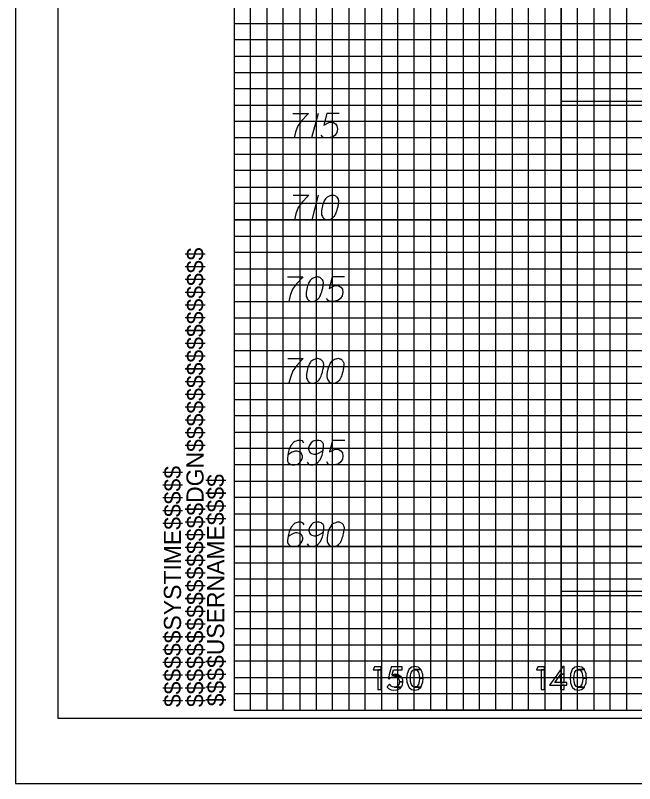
# Model space of a CAD drawing. Extents: x -13 to 323, y -5 to 1431.
# Drawn here: x -13.4 to 24.5, y 435.5 to 482.5 of the extents above; entities that cross this region are included whole.
import ezdxf

# ---------------------------------------------------------------- set-up
doc = ezdxf.new("R2010")
doc.units = 0
for name, color, linetype in [('Prop XS Elevation Labels', 7, 'Continuous'), ('Prop XS Offset Labels', 7, 'Continuous'), ('Scratch_Level_3', 7, 'Continuous'), ('Sheet Cross Section CELL', 7, 'Continuous'), ('Sheet Cross Section Grid Major CELL', 7, 'Continuous'), ('Sheet Cross Section Grid Middle CELL', 7, 'Continuous'), ('Sheet Cross Section Grid Minor 1 CELL', 7, 'Continuous'), ('Sheet Cross Section Grid Minor 2 CELL', 7, 'Continuous'), ('Sheet Cutting Line CELL', 7, 'Continuous'), ('Sheet DOT Grid CELL', 7, 'Continuous'), ('Sheet Plot Border Inside CELL', 7, 'Continuous'), ('Sheet Plot Border Outside CELL', 7, 'Continuous')]:
    doc.layers.add(name, color=color, linetype=linetype)

msp = doc.modelspace()

# ---------------------------------------------------------------- linework, layer by layer
at = {"layer": 'Prop XS Elevation Labels'}
for p, q in [((5.124, 476.5), (4.723, 475)), ((5.142, 471.5), (4.74, 470))]:
    msp.add_line(p, q, dxfattribs=at)
for points in [[(3.589, 476.5), (4.533, 476.5), (4.474, 476.441), (4.132, 476.075), (3.896, 475.744), (3.754, 475.354), (3.659, 475)], [(6.411, 476.5), (5.667, 476.5), (5.478, 475.791), (5.821, 475.969), (6.022, 475.969), (6.187, 475.862), (6.282, 475.744), (6.305, 475.543), (6.27, 475.342), (6.175, 475.177), (6.01, 475.047), (5.726, 475), (5.514, 475), (5.408, 475.047), (5.313, 475.177)], [(3.606, 471.5), (4.551, 471.5), (4.492, 471.441), (4.149, 471.075), (3.913, 470.744), (3.772, 470.354), (3.677, 470)], [(6.039, 471.5), (6.016, 471.5), (5.945, 471.488), (5.898, 471.476), (5.862, 471.465), (5.803, 471.441), (5.732, 471.406), (5.673, 471.37), (5.614, 471.323), (5.579, 471.276), (5.543, 471.217), (5.508, 471.158), (5.472, 471.087), (5.449, 471.039), (5.425, 470.969), (5.39, 470.85), (5.354, 470.673), (5.331, 470.531), (5.331, 470.402), (5.343, 470.307), (5.39, 470.201), (5.425, 470.142), (5.484, 470.071), (5.555, 470.024), (5.591, 470.012), (5.661, 470), (5.72, 470), (5.815, 470.012), (5.898, 470.035), (5.957, 470.071), (6.039, 470.13), (6.075, 470.165), (6.122, 470.213), (6.157, 470.26), (6.181, 470.295), (6.205, 470.354), (6.217, 470.378), (6.24, 470.437), (6.264, 470.508), (6.287, 470.579), (6.299, 470.626), (6.311, 470.661), (6.323, 470.709), (6.347, 470.815), (6.358, 470.874), (6.37, 470.933), (6.382, 471.016), (6.394, 471.122), (6.394, 471.158), (6.382, 471.205), (6.37, 471.252), (6.335, 471.323), (6.299, 471.37), (6.264, 471.406), (6.217, 471.441), (6.169, 471.465), (6.134, 471.476), (6.098, 471.488), (6.039, 471.5)], [(3.258, 466.5), (4.203, 466.5), (4.144, 466.441), (3.801, 466.075), (3.565, 465.744), (3.423, 465.354), (3.329, 465)], [(5.1, 466.5), (5.077, 466.5), (5.006, 466.488), (4.959, 466.476), (4.923, 466.465), (4.864, 466.441), (4.793, 466.406), (4.734, 466.37), (4.675, 466.323), (4.64, 466.276), (4.604, 466.217), (4.569, 466.158), (4.534, 466.087), (4.51, 466.039), (4.486, 465.969), (4.451, 465.85), (4.415, 465.673), (4.392, 465.531), (4.392, 465.402), (4.404, 465.307), (4.451, 465.201), (4.486, 465.142), (4.545, 465.071), (4.616, 465.024), (4.652, 465.012), (4.723, 465), (4.781, 465), (4.876, 465.012), (4.959, 465.035), (5.018, 465.071), (5.1, 465.13), (5.136, 465.165), (5.183, 465.213), (5.219, 465.26), (5.242, 465.295), (5.266, 465.354), (5.278, 465.378), (5.301, 465.437), (5.325, 465.508), (5.349, 465.579), (5.36, 465.626), (5.372, 465.661), (5.384, 465.709), (5.408, 465.815), (5.419, 465.874), (5.431, 465.933), (5.443, 466.016), (5.455, 466.122), (5.455, 466.158), (5.443, 466.205), (5.431, 466.252), (5.396, 466.323), (5.36, 466.37), (5.325, 466.406), (5.278, 466.441), (5.23, 466.465), (5.195, 466.476), (5.16, 466.488), (5.1, 466.5)], [(6.742, 466.5), (5.998, 466.5), (5.809, 465.791), (6.152, 465.969), (6.352, 465.969), (6.518, 465.862), (6.612, 465.744), (6.636, 465.543), (6.6, 465.342), (6.506, 465.177), (6.341, 465.047), (6.057, 465), (5.845, 465), (5.738, 465.047), (5.644, 465.177)], [(3.276, 461.5), (4.22, 461.5), (4.161, 461.441), (3.819, 461.075), (3.583, 460.744), (3.441, 460.354), (3.346, 460)], [(5.118, 461.5), (5.094, 461.5), (5.024, 461.488), (4.977, 461.476), (4.941, 461.465), (4.882, 461.441), (4.811, 461.406), (4.752, 461.37), (4.693, 461.323), (4.658, 461.276), (4.622, 461.217), (4.587, 461.158), (4.551, 461.087), (4.528, 461.039), (4.504, 460.969), (4.469, 460.85), (4.433, 460.673), (4.409, 460.531), (4.409, 460.402), (4.421, 460.307), (4.469, 460.201), (4.504, 460.142), (4.563, 460.071), (4.634, 460.024), (4.669, 460.012), (4.74, 460), (4.799, 460), (4.894, 460.012), (4.977, 460.035), (5.036, 460.071), (5.118, 460.13), (5.154, 460.165), (5.201, 460.213), (5.236, 460.26), (5.26, 460.295), (5.283, 460.354), (5.295, 460.378), (5.319, 460.437), (5.342, 460.508), (5.366, 460.579), (5.378, 460.626), (5.39, 460.661), (5.402, 460.709), (5.425, 460.815), (5.437, 460.874), (5.449, 460.933), (5.461, 461.016), (5.473, 461.122), (5.473, 461.158), (5.461, 461.205), (5.449, 461.252), (5.413, 461.323), (5.378, 461.37), (5.342, 461.406), (5.295, 461.441), (5.248, 461.465), (5.213, 461.476), (5.177, 461.488), (5.118, 461.5)], [(6.37, 461.5), (6.346, 461.5), (6.276, 461.488), (6.228, 461.476), (6.193, 461.465), (6.134, 461.441), (6.063, 461.406), (6.004, 461.37), (5.945, 461.323), (5.909, 461.276), (5.874, 461.217), (5.838, 461.158), (5.803, 461.087), (5.779, 461.039), (5.756, 460.969), (5.721, 460.85), (5.685, 460.673), (5.661, 460.531), (5.661, 460.402), (5.673, 460.307), (5.721, 460.201), (5.756, 460.142), (5.815, 460.071), (5.886, 460.024), (5.921, 460.012), (5.992, 460), (6.051, 460), (6.146, 460.012), (6.228, 460.035), (6.287, 460.071), (6.37, 460.13), (6.406, 460.165), (6.453, 460.213), (6.488, 460.26), (6.512, 460.295), (6.535, 460.354), (6.547, 460.378), (6.571, 460.437), (6.594, 460.508), (6.618, 460.579), (6.63, 460.626), (6.642, 460.661), (6.653, 460.709), (6.677, 460.815), (6.689, 460.874), (6.701, 460.933), (6.713, 461.016), (6.724, 461.122), (6.724, 461.158), (6.713, 461.205), (6.701, 461.252), (6.665, 461.323), (6.63, 461.37), (6.594, 461.406), (6.547, 461.441), (6.5, 461.465), (6.464, 461.476), (6.429, 461.488), (6.37, 461.5)], [(4.262, 456.335), (4.168, 456.465), (4.061, 456.5), (3.896, 456.5), (3.778, 456.453), (3.707, 456.429), (3.648, 456.394), (3.459, 456.181), (3.329, 455.898), (3.294, 455.744), (3.246, 455.402), (3.246, 455.224), (3.294, 455.154), (3.388, 455.059), (3.423, 455.035), (3.542, 455), (3.695, 455), (3.813, 455.024), (3.896, 455.047), (4.014, 455.142), (4.132, 455.331), (4.168, 455.449), (4.168, 455.543), (4.109, 455.697), (4.061, 455.756), (3.979, 455.803), (3.837, 455.839), (3.73, 455.839), (3.601, 455.803), (3.518, 455.768), (3.376, 455.673), (3.305, 455.614), (3.27, 455.579)], [(4.451, 455.165), (4.545, 455.035), (4.652, 455), (4.817, 455), (4.935, 455.047), (5.006, 455.071), (5.065, 455.106), (5.254, 455.319), (5.384, 455.602), (5.419, 455.756), (5.467, 456.098), (5.467, 456.276), (5.419, 456.346), (5.325, 456.441), (5.289, 456.465), (5.171, 456.5), (5.018, 456.5), (4.9, 456.476), (4.817, 456.453), (4.699, 456.358), (4.581, 456.169), (4.545, 456.051), (4.545, 455.957), (4.604, 455.803), (4.652, 455.744), (4.734, 455.697), (4.876, 455.661), (4.982, 455.661), (5.112, 455.697), (5.195, 455.732), (5.337, 455.827), (5.408, 455.886), (5.443, 455.921)], [(6.754, 456.5), (6.01, 456.5), (5.821, 455.791), (6.163, 455.969), (6.364, 455.969), (6.529, 455.862), (6.624, 455.744), (6.647, 455.543), (6.612, 455.342), (6.517, 455.177), (6.352, 455.047), (6.069, 455), (5.856, 455), (5.75, 455.047), (5.655, 455.177)], [(4.28, 451.335), (4.185, 451.465), (4.079, 451.5), (3.914, 451.5), (3.795, 451.453), (3.725, 451.429), (3.666, 451.394), (3.477, 451.181), (3.347, 450.898), (3.311, 450.744), (3.264, 450.402), (3.264, 450.224), (3.311, 450.154), (3.406, 450.059), (3.441, 450.035), (3.559, 450), (3.713, 450), (3.831, 450.024), (3.914, 450.047), (4.032, 450.142), (4.15, 450.331), (4.185, 450.449), (4.185, 450.543), (4.126, 450.697), (4.079, 450.756), (3.996, 450.803), (3.854, 450.839), (3.748, 450.839), (3.618, 450.803), (3.536, 450.768), (3.394, 450.673), (3.323, 450.614), (3.288, 450.579)], [(4.468, 450.165), (4.563, 450.035), (4.669, 450), (4.835, 450), (4.953, 450.047), (5.024, 450.071), (5.083, 450.106), (5.272, 450.319), (5.401, 450.602), (5.437, 450.756), (5.484, 451.098), (5.484, 451.276), (5.437, 451.346), (5.342, 451.441), (5.307, 451.465), (5.189, 451.5), (5.036, 451.5), (4.917, 451.476), (4.835, 451.453), (4.717, 451.358), (4.598, 451.169), (4.563, 451.051), (4.563, 450.957), (4.622, 450.803), (4.669, 450.744), (4.752, 450.697), (4.894, 450.661), (5, 450.661), (5.13, 450.697), (5.213, 450.732), (5.354, 450.827), (5.425, 450.886), (5.461, 450.921)], [(6.382, 451.5), (6.358, 451.5), (6.287, 451.488), (6.24, 451.476), (6.204, 451.465), (6.145, 451.441), (6.074, 451.406), (6.015, 451.37), (5.956, 451.323), (5.921, 451.276), (5.885, 451.217), (5.85, 451.158), (5.815, 451.087), (5.791, 451.039), (5.767, 450.969), (5.732, 450.85), (5.697, 450.673), (5.673, 450.531), (5.673, 450.402), (5.685, 450.307), (5.732, 450.201), (5.767, 450.142), (5.827, 450.071), (5.897, 450.024), (5.933, 450.012), (6.004, 450), (6.063, 450), (6.157, 450.012), (6.24, 450.035), (6.299, 450.071), (6.382, 450.13), (6.417, 450.165), (6.464, 450.213), (6.5, 450.26), (6.523, 450.295), (6.547, 450.354), (6.559, 450.378), (6.582, 450.437), (6.606, 450.508), (6.63, 450.579), (6.642, 450.626), (6.653, 450.661), (6.665, 450.709), (6.689, 450.815), (6.701, 450.874), (6.712, 450.933), (6.724, 451.016), (6.736, 451.122), (6.736, 451.158), (6.724, 451.205), (6.712, 451.252), (6.677, 451.323), (6.642, 451.37), (6.606, 451.406), (6.559, 451.441), (6.512, 451.465), (6.476, 451.476), (6.441, 451.488), (6.382, 451.5)]]:
    msp.add_lwpolyline(points, dxfattribs=at)
at = {"layer": 'Prop XS Offset Labels'}
for points in [[(8.581, 442.641), (8.492, 442.459), (8.99, 442.459), (8.99, 442.641)], [(8.781, 442.459), (8.781, 441.25), (8.99, 441.25), (8.99, 442.459)], [(9.427, 441.94), (9.424, 441.928), (9.495, 441.928), (9.508, 441.94), (9.524, 441.954), (9.595, 441.997), (9.627, 442.007), (9.697, 442.029), (9.811, 442.035), (10.219, 442.035), (10.211, 442.05), (10.076, 442.145), (9.655, 442.145), (9.658, 442.158), (9.658, 442.158), (9.663, 442.178), (9.738, 442.456), (10.263, 442.456), (10.263, 442.641), (9.6, 442.641), (9.554, 442.456), (9.486, 442.178), (9.481, 442.158), (9.478, 442.145), (9.454, 442.05), (9.451, 442.035), (9.449, 442.029), (9.444, 442.007), (9.441, 441.997), (9.431, 441.954)], [(10.851, 441.255), (11.051, 441.214), (11.245, 441.255), (11.256, 441.257), (11.422, 441.409), (11.047, 441.409), (11.038, 441.411), (11.033, 441.413), (10.928, 441.442), (10.841, 441.555), (10.841, 441.556), (10.841, 441.556), (10.813, 441.657), (10.813, 441.659), (10.793, 441.732), (10.792, 441.736), (10.774, 441.939), (10.774, 441.941), (10.774, 441.943), (10.792, 442.145), (10.812, 442.222), (10.813, 442.224), (10.839, 442.322), (10.84, 442.325), (10.928, 442.44), (11.041, 442.469), (11.045, 442.47), (11.055, 442.473), (11.425, 442.473), (11.262, 442.622), (11.254, 442.624), (11.053, 442.668), (11.053, 442.668), (10.845, 442.624), (10.843, 442.622), (10.681, 442.473), (10.678, 442.47), (10.678, 442.469), (10.665, 442.44), (10.618, 442.325), (10.617, 442.322), (10.577, 442.224), (10.576, 442.222), (10.568, 442.145), (10.547, 441.943), (10.547, 441.941), (10.547, 441.939), (10.567, 441.736), (10.568, 441.732), (10.575, 441.659), (10.575, 441.657), (10.616, 441.556), (10.617, 441.555), (10.663, 441.442), (10.675, 441.413), (10.676, 441.411), (10.679, 441.409), (10.848, 441.257)], [(11.312, 442.145), (11.328, 441.943), (11.555, 441.943), (11.536, 442.145), (11.528, 442.222), (11.527, 442.224), (11.527, 442.224), (11.488, 442.322), (11.488, 442.322), (11.487, 442.325), (11.441, 442.44), (11.44, 442.44), (11.429, 442.469), (11.428, 442.47), (11.425, 442.473), (11.055, 442.473), (11.065, 442.47), (11.068, 442.469), (11.175, 442.44), (11.262, 442.325), (11.265, 442.322), (11.291, 442.224), (11.291, 442.222)], [(18.581, 442.641), (18.492, 442.459), (18.99, 442.459), (18.99, 442.641)], [(18.781, 442.459), (18.781, 441.25), (18.99, 441.25), (18.99, 442.459)], [(19.411, 441.693), (19.297, 441.534), (20.35, 441.534), (20.35, 441.693), (19.618, 441.693), (19.878, 442.059), (19.935, 442.139), (19.977, 442.199), (20.179, 442.199), (20.179, 442.668), (20.114, 442.668), (19.775, 442.199), (19.733, 442.139), (19.675, 442.059)], [(20.851, 441.255), (21.051, 441.214), (21.245, 441.255), (21.256, 441.257), (21.422, 441.409), (21.047, 441.409), (21.038, 441.411), (21.033, 441.413), (20.928, 441.442), (20.841, 441.555), (20.841, 441.556), (20.841, 441.556), (20.813, 441.657), (20.813, 441.659), (20.793, 441.732), (20.792, 441.736), (20.774, 441.939), (20.774, 441.941), (20.774, 441.943), (20.792, 442.145), (20.812, 442.222), (20.813, 442.224), (20.839, 442.322), (20.84, 442.325), (20.928, 442.44), (21.041, 442.469), (21.045, 442.47), (21.055, 442.473), (21.425, 442.473), (21.262, 442.622), (21.254, 442.624), (21.053, 442.668), (21.053, 442.668), (20.845, 442.624), (20.843, 442.622), (20.681, 442.473), (20.678, 442.47), (20.678, 442.469), (20.665, 442.44), (20.618, 442.325), (20.617, 442.322), (20.577, 442.224), (20.576, 442.222), (20.568, 442.145), (20.547, 441.943), (20.547, 441.941), (20.547, 441.939), (20.567, 441.736), (20.567, 441.732), (20.575, 441.659), (20.575, 441.657), (20.616, 441.556), (20.617, 441.555), (20.663, 441.442), (20.675, 441.413), (20.676, 441.411), (20.679, 441.409), (20.848, 441.257)], [(21.312, 442.145), (21.328, 441.943), (21.555, 441.943), (21.536, 442.145), (21.528, 442.222), (21.527, 442.224), (21.527, 442.224), (21.488, 442.322), (21.488, 442.322), (21.487, 442.325), (21.441, 442.44), (21.44, 442.44), (21.429, 442.469), (21.428, 442.47), (21.425, 442.473), (21.055, 442.473), (21.065, 442.47), (21.068, 442.469), (21.175, 442.44), (21.262, 442.325), (21.265, 442.322), (21.291, 442.224), (21.291, 442.222)], [(9.424, 441.928), (9.482, 441.916), (9.495, 441.928)], [(9.692, 442.158), (9.655, 442.145), (10.076, 442.145), (10.058, 442.158), (9.961, 442.178), (9.75, 442.178)], [(9.888, 442.192), (9.75, 442.178), (9.96, 442.178), (9.888, 442.192)], [(10.083, 441.841), (10.105, 441.721), (10.318, 441.721), (10.307, 441.841), (10.307, 441.841), (10.303, 441.881), (10.284, 441.916), (10.278, 441.928), (10.271, 441.94), (10.263, 441.954), (10.24, 441.997), (10.235, 442.007), (10.223, 442.029), (10.219, 442.035), (9.811, 442.035), (9.838, 442.029), (9.928, 442.007), (9.943, 441.997), (10.003, 441.954), (10.024, 441.94), (10.031, 441.928), (10.038, 441.916), (10.059, 441.881)], [(11.058, 441.411), (11.047, 441.409), (11.422, 441.409), (11.425, 441.411), (11.426, 441.413), (11.438, 441.442), (11.485, 441.555), (11.485, 441.556), (11.527, 441.657), (11.528, 441.659), (11.535, 441.732), (11.535, 441.736), (11.555, 441.939), (11.556, 441.941), (11.555, 441.943), (11.328, 441.943), (11.328, 441.941), (11.328, 441.939), (11.312, 441.736), (11.312, 441.732), (11.292, 441.659), (11.291, 441.657), (11.264, 441.556), (11.263, 441.555), (11.175, 441.442), (11.063, 441.413)], [(19.97, 442.059), (19.97, 441.693), (20.179, 441.693), (20.179, 442.059), (20.179, 442.139), (20.179, 442.199), (19.977, 442.199), (19.973, 442.139)], [(21.058, 441.411), (21.047, 441.409), (21.422, 441.409), (21.425, 441.411), (21.426, 441.413), (21.438, 441.442), (21.485, 441.555), (21.485, 441.556), (21.527, 441.657), (21.528, 441.659), (21.535, 441.732), (21.535, 441.736), (21.555, 441.939), (21.556, 441.941), (21.555, 441.943), (21.328, 441.943), (21.328, 441.941), (21.328, 441.939), (21.312, 441.736), (21.312, 441.732), (21.292, 441.659), (21.291, 441.657), (21.264, 441.556), (21.263, 441.555), (21.175, 441.442), (21.063, 441.413)], [(9.626, 441.233), (9.762, 441.214), (9.959, 441.233), (9.968, 441.237), (10.091, 441.297), (10.091, 441.297), (10.141, 441.321), (10.185, 441.375), (10.204, 441.399), (9.793, 441.399), (9.683, 441.418), (9.682, 441.419), (9.679, 441.42), (9.596, 441.466), (9.586, 441.477), (9.58, 441.483), (9.58, 441.483), (9.529, 441.535), (9.497, 441.585), (9.497, 441.585), (9.451, 441.535), (9.404, 441.483), (9.399, 441.477), (9.39, 441.466), (9.348, 441.42), (9.347, 441.419), (9.348, 441.418), (9.363, 441.399), (9.382, 441.375), (9.445, 441.321), (9.474, 441.297), (9.598, 441.237)], [(9.9, 441.418), (9.793, 441.399), (10.204, 441.399), (10.22, 441.418), (10.221, 441.419), (10.222, 441.42), (10.222, 441.42), (10.259, 441.466), (10.268, 441.477), (10.27, 441.483), (10.284, 441.535), (10.299, 441.59), (10.322, 441.674), (10.318, 441.721), (10.105, 441.721), (10.097, 441.674), (10.082, 441.59), (10.047, 441.535), (10.014, 441.483), (10.004, 441.477), (9.987, 441.466), (9.913, 441.42), (9.905, 441.419)], [(19.97, 441.534), (19.97, 441.25), (20.179, 441.25), (20.179, 441.534)]]:
    msp.add_lwpolyline(points, close=True, dxfattribs=at)
at = {"layer": 'Scratch_Level_3'}
msp.add_lwpolyline([(20, 477.248), (300, 477.248), (300, 447.248), (20, 447.248)], close=True, dxfattribs=at)
at = {"layer": 'Sheet Cross Section CELL'}
msp.add_line((0, 440), (0, 440), dxfattribs=at)
msp.add_line((0, 440), (0, 440), dxfattribs=at)
msp.add_line((0, 440), (0, 440), dxfattribs=at)
msp.add_line((0, 440), (0, 440), dxfattribs=at)
msp.add_line((0, 440), (0, 440), dxfattribs=at)
msp.add_line((0, 440), (0, 440), dxfattribs=at)
msp.add_line((0, 440), (0, 440), dxfattribs=at)
msp.add_lwpolyline([(320, 650), (0, 650), (0, 440), (320, 440)], close=True, dxfattribs=at)
at = {"layer": 'Sheet Cross Section Grid Major CELL'}
for p, q in [((10, 440), (10, 650)), ((20, 650), (20, 440)), ((20, 440), (10, 440))]:
    msp.add_line(p, q, dxfattribs=at)
for points in [[(0, 480), (320, 480), (320, 470), (0, 470)], [(0, 460), (320, 460), (320, 450), (0, 450)]]:
    msp.add_lwpolyline(points, dxfattribs=at)
at = {"layer": 'Sheet Cross Section Grid Middle CELL'}
for points in [[(5, 650), (5, 440), (15, 440), (15, 650)], [(0, 465), (320, 465), (320, 475), (0, 475)], [(0, 445), (320, 445), (320, 455), (0, 455)]]:
    msp.add_lwpolyline(points, dxfattribs=at)
at = {"layer": 'Sheet Cross Section Grid Minor 1 CELL'}
for points in [[(0, 482), (320, 482), (320, 481), (0, 481)], [(0, 479), (320, 479), (320, 478), (0, 478)], [(0, 477), (320, 477), (320, 476), (0, 476)], [(0, 474), (320, 474), (320, 473), (0, 473)], [(0, 472), (320, 472), (320, 471), (0, 471)], [(0, 469), (320, 469), (320, 468), (0, 468)], [(0, 467), (320, 467), (320, 466), (0, 466)], [(0, 464), (320, 464), (320, 463), (0, 463)], [(0, 462), (320, 462), (320, 461), (0, 461)], [(0, 459), (320, 459), (320, 458), (0, 458)], [(0, 457), (320, 457), (320, 456), (0, 456)], [(0, 454), (320, 454), (320, 453), (0, 453)], [(0, 452), (320, 452), (320, 451), (0, 451)], [(0, 449), (320, 449), (320, 448), (0, 448)], [(0, 447), (320, 447), (320, 446), (0, 446)], [(0, 444), (320, 444), (320, 443), (0, 443)], [(0, 442), (320, 442), (320, 441), (0, 441)]]:
    msp.add_lwpolyline(points, dxfattribs=at)
at = {"layer": 'Sheet Cross Section Grid Minor 2 CELL'}
for points in [[(0, 440), (1, 440), (1, 650), (2, 650), (2, 440)], [(2, 440), (3, 440), (3, 650), (4, 650), (4, 440)], [(5, 440), (6, 440), (6, 650), (7, 650), (7, 440)], [(7, 440), (8, 440), (8, 650), (9, 650), (9, 440)], [(10, 440), (11, 440), (11, 650), (12, 650), (12, 440)], [(12, 440), (13, 440), (13, 650), (14, 650), (14, 440)], [(15, 440), (16, 440), (16, 650), (17, 650), (17, 440)], [(17, 440), (18, 440), (18, 650), (19, 650), (19, 440)], [(20, 440), (21, 440), (21, 650), (22, 650), (22, 440)], [(22, 440), (23, 440), (23, 650), (24, 650), (24, 440)]]:
    msp.add_lwpolyline(points, dxfattribs=at)
at = {"layer": 'Sheet Cutting Line CELL'}
for p, q in [((-13.4, 654.5), (-13.4, 435.5)), ((-13.4, 435.5), (323.3, 435.5))]:
    msp.add_line(p, q, dxfattribs=at)
at = {"layer": 'Sheet DOT Grid CELL'}
for p, q in [((10, 440), (10, 650)), ((20, 440), (20, 650)), ((0, 480), (320, 480)), ((0, 470), (320, 470)), ((0, 460), (320, 460)), ((0, 450), (320, 450))]:
    msp.add_line(p, q, dxfattribs=at)
at = {"layer": 'Sheet Plot Border Inside CELL'}
msp.add_lwpolyline([(-10.8, 439.5), (322.4, 439.5), (322.4, 650.5), (-10.8, 650.5)], close=True, dxfattribs=at)
at = {"layer": 'Sheet Plot Border Outside CELL'}
msp.add_lwpolyline([(-13.4, 435.5), (323.3, 435.5), (323.3, 654.5), (-13.4, 654.5)], close=True, dxfattribs=at)

# ---------------------------------------------------------------- texts
at = {"layer": 'Sheet Cross Section CELL'}
for s, p in [('$$$$$$$$$$$$$$$$DGN$$$$$$$$$$$$$$$$', (-1.88, 440.18)), ('$$$$$$SYSTIME$$$$$', (-3.26, 440.18)), ('$$$$USERNAME$$$$', (-0.62, 440.23))]:
    msp.add_text(s, height=1.05, rotation=90, dxfattribs=at).set_placement(p)

doc.saveas('drawing.dxf')
